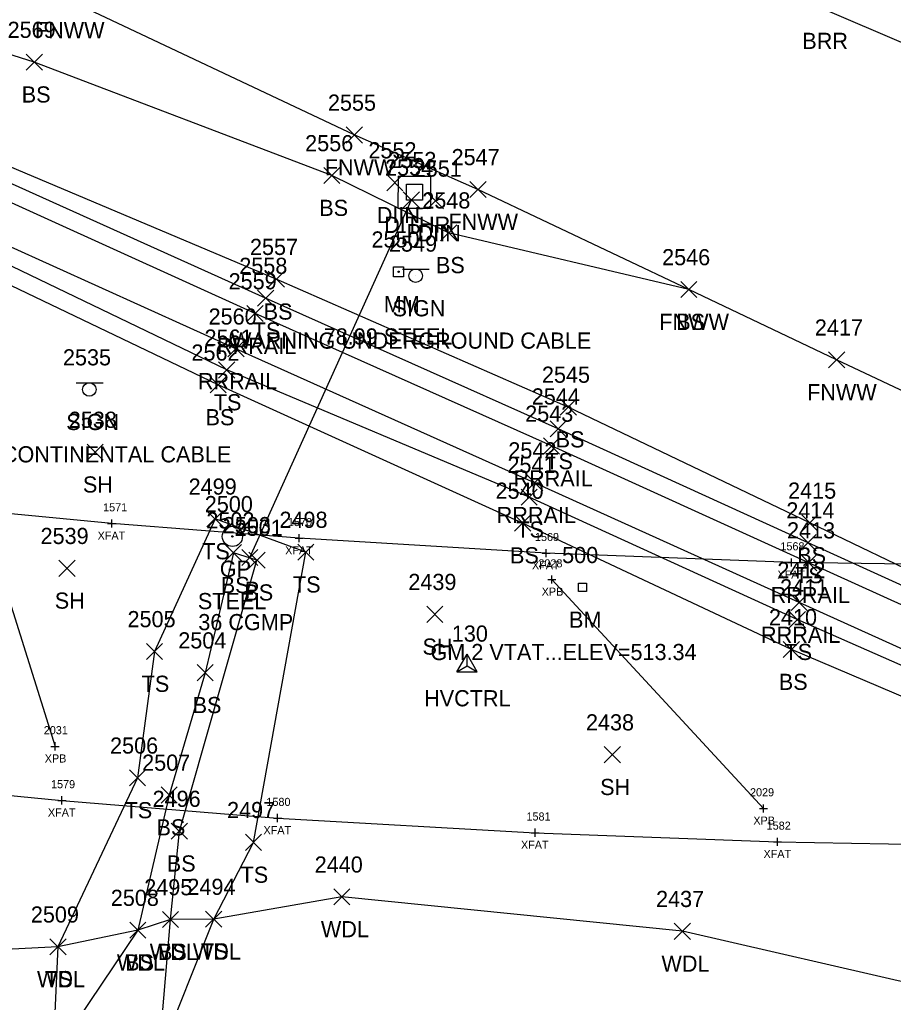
# Model space of a CAD drawing. Extents: x 1599569 to 1610055, y 642560 to 647860.
# Drawn here: x 1601194.8 to 1601302.9, y 647218.7 to 647340.3 of the extents above; entities that cross this region are included whole.
import ezdxf

# ---------------------------------------------------------------- set-up
doc = ezdxf.new("R2010")
doc.units = 0
for name, color, linetype in [('B_A', 7, 'Continuous'), ('B_I', 7, 'Continuous'), ('B_TIC', 7, 'Continuous'), ('BF', 7, 'Continuous'), ('BSUBM', 7, 'Continuous'), ('C_A', 7, 'Continuous'), ('C_C', 7, 'Continuous'), ('C_I', 7, 'Continuous'), ('CPBM', 7, 'Continuous'), ('CPSM', 7, 'Continuous'), ('D_A', 7, 'Continuous'), ('D_C', 7, 'Continuous'), ('D_I', 7, 'Continuous'), ('D_TIC', 7, 'Continuous'), ('DCP', 7, 'Continuous'), ('DS', 7, 'Continuous'), ('L_A', 7, 'Continuous'), ('L_I', 7, 'Continuous'), ('L_TIC', 7, 'Continuous'), ('LABL', 7, 'Continuous'), ('LAWA', 7, 'Continuous'), ('LELB', 7, 'Continuous'), ('LFNC', 7, 'Continuous'), ('R_A', 7, 'Continuous'), ('R_C', 7, 'Continuous'), ('R_I', 7, 'Continuous'), ('R_TIC', 7, 'Continuous'), ('RGP', 7, 'Continuous'), ('RR', 7, 'Continuous'), ('S_A', 7, 'Continuous'), ('S_C', 7, 'Continuous'), ('S_I', 7, 'Continuous'), ('SRM', 7, 'Continuous'), ('SSGN', 7, 'Continuous')]:
    doc.layers.add(name, color=color, linetype=linetype)

msp = doc.modelspace()

# ---------------------------------------------------------------- linework, layer by layer
at = {"layer": 'B_TIC'}
for p, q in [((1601206.23, 647277.99), (1601206.3, 647277.99)), ((1601229.43, 647276.17), (1601229.51, 647276.17)), ((1601259.98, 647274.32), (1601260.05, 647274.32)), ((1601290.34, 647273.17), (1601290.42, 647273.17)), ((1601260.69, 647271.06), (1601260.77, 647271.06)), ((1601199.21, 647250.42), (1601199.29, 647250.42)), ((1601200.08, 647243.74), (1601200.15, 647243.74)), ((1601286.89, 647242.74), (1601286.96, 647242.74)), ((1601226.76, 647241.55), (1601226.84, 647241.55)), ((1601258.62, 647239.74), (1601258.69, 647239.74)), ((1601288.62, 647238.61), (1601288.7, 647238.61))]:
    msp.add_line(p, q, dxfattribs=at)
for points in [[(1601206.22, 647277.49), (1601206.22, 647278.49)], [(1601205.72, 647277.99), (1601206.72, 647277.99)], [(1601228.93, 647276.17), (1601229.93, 647276.17)], [(1601229.43, 647275.67), (1601229.43, 647276.67)], [(1601259.98, 647273.82), (1601259.98, 647274.82)], [(1601259.48, 647274.32), (1601260.48, 647274.32)], [(1601290.34, 647272.67), (1601290.34, 647273.67)], [(1601289.84, 647273.17), (1601290.84, 647273.17)], [(1601260.19, 647271.06), (1601261.19, 647271.06)], [(1601260.69, 647270.56), (1601260.69, 647271.56)], [(1601198.71, 647250.42), (1601199.71, 647250.42)], [(1601199.21, 647249.92), (1601199.21, 647250.92)], [(1601200.07, 647243.24), (1601200.07, 647244.24)], [(1601199.57, 647243.74), (1601200.57, 647243.74)], [(1601286.88, 647242.24), (1601286.88, 647243.24)], [(1601226.76, 647241.05), (1601226.76, 647242.05)], [(1601286.38, 647242.74), (1601287.38, 647242.74)], [(1601226.26, 647241.55), (1601227.26, 647241.55)], [(1601258.11, 647239.74), (1601259.11, 647239.74)], [(1601258.61, 647239.24), (1601258.61, 647240.24)], [(1601288.12, 647238.61), (1601289.12, 647238.61)], [(1601288.62, 647238.11), (1601288.62, 647239.11)]]:
    msp.add_lwpolyline(points, dxfattribs=at)
at = {"layer": 'BF'}
for points in [[(1601321.94, 647272.73), (1601290.34, 647273.17), (1601259.98, 647274.32), (1601229.43, 647276.17), (1601206.22, 647277.99), (1601191.16, 647279.44), (1601163.73, 647282.21), (1601139.85, 647285.25), (1601124.64, 647287.26)], [(1601119.61, 647253.21), (1601149.88, 647249.04), (1601178.06, 647245.86), (1601200.07, 647243.74), (1601226.76, 647241.55), (1601258.61, 647239.74), (1601288.62, 647238.61), (1601320.66, 647238.01)]]:
    msp.add_lwpolyline(points, dxfattribs=at)
at = {"layer": 'BSUBM'}
for points in [[(1601192.25, 647272.5), (1601199.21, 647250.42)], [(1601260.69, 647271.06), (1601286.88, 647242.74)]]:
    msp.add_lwpolyline(points, dxfattribs=at)
at = {"layer": 'CPBM'}
for p, q in [((1601263.99, 647269.59), (1601263.99, 647270.59)), ((1601263.99, 647270.59), (1601264.99, 647270.59)), ((1601264.49, 647270.09), (1601264.49, 647270.09)), ((1601264.49, 647270.09), (1601264.49, 647270.09)), ((1601264.99, 647270.59), (1601264.99, 647269.59)), ((1601264.99, 647269.59), (1601263.99, 647269.59))]:
    msp.add_line(p, q, dxfattribs=at)
at = {"layer": 'CPSM'}
for p, q in [((1601248.94, 647259.65), (1601250.19, 647261.82)), ((1601251.44, 647259.65), (1601250.19, 647261.82)), ((1601250.19, 647260.37), (1601250.19, 647261.82)), ((1601248.94, 647259.65), (1601250.19, 647260.37)), ((1601250.19, 647260.37), (1601250.19, 647260.37)), ((1601250.19, 647260.37), (1601251.44, 647259.65)), ((1601248.94, 647259.65), (1601251.44, 647259.65))]:
    msp.add_line(p, q, dxfattribs=at)
at = {"layer": 'D_TIC'}
for points in [[(1601240.25, 647319.16), (1601242.25, 647321.16)], [(1601242.25, 647319.16), (1601240.25, 647321.16)], [(1601242.31, 647317.03), (1601244.31, 647319.03)], [(1601244.31, 647317.03), (1601242.31, 647319.03)], [(1601245.29, 647316.9), (1601247.29, 647318.9)], [(1601247.29, 647316.9), (1601245.29, 647318.9)], [(1601222.31, 647272.79), (1601224.31, 647274.79)], [(1601224.31, 647272.79), (1601222.31, 647274.79)]]:
    msp.add_lwpolyline(points, dxfattribs=at)
at = {"layer": 'DCP'}
msp.add_lwpolyline([(1601223.31, 647273.79), (1601243.31, 647318.03)], dxfattribs=at)
at = {"layer": 'DS'}
for p, q in [((1601241.69, 647320.98), (1601245.69, 647320.98)), ((1601241.69, 647316.98), (1601241.71, 647320.98)), ((1601245.69, 647320.98), (1601245.69, 647316.98)), ((1601242.69, 647319.98), (1601244.69, 647319.98)), ((1601242.69, 647317.98), (1601242.69, 647319.98)), ((1601244.69, 647319.98), (1601244.69, 647317.98)), ((1601243.7, 647318.99), (1601243.7, 647318.99)), ((1601244.69, 647317.98), (1601242.69, 647317.98)), ((1601245.69, 647316.98), (1601241.69, 647316.98)), ((1601244.19, 647316.98), (1601244.69, 647316.98))]:
    msp.add_line(p, q, dxfattribs=at)
at = {"layer": 'L_TIC'}
for points in [[(1601195.65, 647334.07), (1601197.65, 647336.07)], [(1601197.65, 647334.07), (1601195.65, 647336.07)], [(1601235.24, 647325.06), (1601237.24, 647327.06)], [(1601237.24, 647325.06), (1601235.24, 647327.06)], [(1601232.47, 647320.04), (1601234.47, 647322.04)], [(1601234.47, 647320.04), (1601232.47, 647322.04)], [(1601250.54, 647318.32), (1601252.54, 647320.32)], [(1601252.54, 647318.32), (1601250.54, 647320.32)], [(1601246.91, 647312.96), (1601248.91, 647314.96)], [(1601248.91, 647312.96), (1601246.91, 647314.96)], [(1601225.59, 647307.21), (1601227.59, 647309.21)], [(1601227.59, 647307.21), (1601225.59, 647309.21)], [(1601276.64, 647305.94), (1601278.64, 647307.94)], [(1601278.64, 647305.94), (1601276.64, 647307.94)], [(1601276.64, 647305.94), (1601278.64, 647307.94)], [(1601278.64, 647305.94), (1601276.64, 647307.94)], [(1601224.27, 647304.87), (1601226.27, 647306.87)], [(1601226.27, 647304.87), (1601224.27, 647306.87)], [(1601294.93, 647297.24), (1601296.93, 647299.24)], [(1601296.93, 647297.24), (1601294.93, 647299.24)], [(1601219.45, 647295.99), (1601221.45, 647297.99)], [(1601221.45, 647295.99), (1601219.45, 647297.99)], [(1601218.4, 647294.14), (1601220.4, 647296.14)], [(1601220.4, 647294.14), (1601218.4, 647296.14)], [(1601261.72, 647291.4), (1601263.72, 647293.4)], [(1601263.72, 647291.4), (1601261.72, 647293.4)], [(1601260.46, 647288.71), (1601262.46, 647290.71)], [(1601262.46, 647288.71), (1601260.46, 647290.71)], [(1601203.17, 647285.82), (1601205.17, 647287.82)], [(1601205.17, 647285.82), (1601203.17, 647287.82)], [(1601256.88, 647280.25), (1601258.88, 647282.25)], [(1601258.88, 647280.25), (1601256.88, 647282.25)], [(1601218.01, 647277.56), (1601220.01, 647279.56)], [(1601220.01, 647277.56), (1601218.01, 647279.56)], [(1601256.07, 647277.05), (1601258.07, 647279.05)], [(1601258.07, 647277.05), (1601256.07, 647279.05)], [(1601291.61, 647277.06), (1601293.61, 647279.06)], [(1601293.61, 647277.06), (1601291.61, 647279.06)], [(1601291.39, 647274.61), (1601293.39, 647276.61)], [(1601293.39, 647274.61), (1601291.39, 647276.61)], [(1601220.28, 647273.38), (1601222.28, 647275.38)], [(1601222.28, 647273.38), (1601220.28, 647275.38)], [(1601229.24, 647273.45), (1601231.24, 647275.45)], [(1601231.24, 647273.45), (1601229.24, 647275.45)], [(1601199.69, 647271.45), (1601201.69, 647273.45)], [(1601201.69, 647271.45), (1601199.69, 647273.45)], [(1601223.2, 647272.46), (1601225.2, 647274.46)], [(1601225.2, 647272.46), (1601223.2, 647274.46)], [(1601245.2, 647265.76), (1601247.2, 647267.76)], [(1601247.2, 647265.76), (1601245.2, 647267.76)], [(1601290.06, 647265.1), (1601292.06, 647267.1)], [(1601292.06, 647265.1), (1601290.06, 647267.1)], [(1601210.52, 647261.16), (1601212.52, 647263.16)], [(1601212.52, 647261.16), (1601210.52, 647263.16)], [(1601289.33, 647261.4), (1601291.33, 647263.4)], [(1601291.33, 647261.4), (1601289.33, 647263.4)], [(1601216.79, 647258.53), (1601218.79, 647260.53)], [(1601218.79, 647258.53), (1601216.79, 647260.53)], [(1601267.17, 647248.39), (1601269.17, 647250.39)], [(1601269.17, 647248.39), (1601267.17, 647250.39)], [(1601208.41, 647245.52), (1601210.41, 647247.52)], [(1601210.41, 647245.52), (1601208.41, 647247.52)], [(1601212.33, 647243.4), (1601214.33, 647245.4)], [(1601214.33, 647243.4), (1601212.33, 647245.4)], [(1601213.6, 647238.93), (1601215.6, 647240.93)], [(1601215.6, 647238.93), (1601213.6, 647240.93)], [(1601222.76, 647237.54), (1601224.76, 647239.54)], [(1601224.76, 647237.54), (1601222.76, 647239.54)], [(1601233.69, 647230.8), (1601235.69, 647232.8)], [(1601235.69, 647230.8), (1601233.69, 647232.8)], [(1601212.51, 647227.99), (1601214.51, 647229.99)], [(1601214.51, 647227.99), (1601212.51, 647229.99)], [(1601212.51, 647227.99), (1601214.51, 647229.99)], [(1601214.51, 647227.99), (1601212.51, 647229.99)], [(1601217.85, 647228.04), (1601219.85, 647230.04)], [(1601219.85, 647228.04), (1601217.85, 647230.04)], [(1601217.85, 647228.04), (1601219.85, 647230.04)], [(1601219.85, 647228.04), (1601217.85, 647230.04)], [(1601208.45, 647226.68), (1601210.45, 647228.68)], [(1601210.45, 647226.68), (1601208.45, 647228.68)], [(1601208.45, 647226.68), (1601210.45, 647228.68)], [(1601210.45, 647226.68), (1601208.45, 647228.68)], [(1601275.84, 647226.54), (1601277.84, 647228.54)], [(1601277.84, 647226.54), (1601275.84, 647228.54)], [(1601198.57, 647224.62), (1601200.57, 647226.62)], [(1601200.57, 647224.62), (1601198.57, 647226.62)], [(1601198.57, 647224.62), (1601200.57, 647226.62)], [(1601200.57, 647224.62), (1601198.57, 647226.62)]]:
    msp.add_lwpolyline(points, dxfattribs=at)
at = {"layer": 'LABL'}
msp.add_lwpolyline([(1601168.99, 647399.27), (1601207.41, 647380.73), (1601257.17, 647358.28), (1601294.19, 647341.7), (1601346.91, 647319.14), (1601374.73, 647304.92), (1601415.9, 647287.21), (1601447.46, 647269.36), (1601451.82, 647260.74), (1601445.32, 647247.33), (1601438.38, 647230.38)], dxfattribs=at)
at = {"layer": 'LAWA'}
msp.add_lwpolyline([(1601306.6, 647220.69), (1601276.84, 647227.54), (1601234.69, 647231.8), (1601218.85, 647229.04), (1601213.51, 647228.99), (1601209.45, 647227.68), (1601199.57, 647225.62), (1601172.91, 647224.25), (1601154.16, 647223.84), (1601131.9, 647227.51), (1601118.99, 647241.56), (1601106.98, 647246.07), (1601045.88, 647251.39), (1601009.79, 647259.81), (1600973.15, 647266.08), (1600946.11, 647265.67), (1600904.1, 647280.51), (1600862.74, 647296.26), (1600826.18, 647313.68), (1600771.19, 647334.59)], dxfattribs=at)
at = {"layer": 'LELB'}
for points in [[(1601329.86, 647260.18), (1601292.61, 647278.06), (1601262.72, 647292.4), (1601226.59, 647308.21), (1601190.68, 647323.36), (1601158.75, 647338.43), (1601129.91, 647351.62), (1601096.68, 647366.43), (1601056.58, 647384.54), (1601012.74, 647404.18), (1600965.22, 647426.07), (1600914.49, 647448.77), (1600866.79, 647471.13), (1600821.34, 647492.23), (1600763.72, 647518.52)], [(1601329.08, 647258.95), (1601292.39, 647275.61), (1601261.46, 647289.71), (1601225.27, 647305.87), (1601190.14, 647321.67), (1601157.62, 647336.35), (1601128.98, 647349.36), (1601095.53, 647364.39), (1601055.96, 647382.57), (1601011.7, 647402.22), (1600964.35, 647423.93), (1600913.28, 647446.74), (1600865.78, 647468.67), (1600819.14, 647488.99), (1600762.95, 647515.26)], [(1601326.17, 647250.65), (1601291.06, 647266.1), (1601257.88, 647281.25), (1601220.45, 647296.99), (1601187.26, 647312.94), (1601153.32, 647328.3), (1601124.87, 647340.95), (1601091.41, 647355.79), (1601053.43, 647373.03), (1601007.18, 647393.84), (1600960.43, 647415.03), (1600909.23, 647438.57), (1600861.95, 647459.92), (1600814.78, 647480.92), (1600758.97, 647506.06)], [(1601324.87, 647247.72), (1601290.33, 647262.4), (1601257.07, 647278.05), (1601219.4, 647295.14), (1601185.88, 647311.18), (1601152.37, 647326.07), (1601123.71, 647338.45), (1601090.36, 647353.63), (1601052.5, 647371.13), (1601006, 647391.96), (1600959.19, 647412.11), (1600907.65, 647435.58), (1600860.78, 647455.97), (1600813.3, 647477.78), (1600757.71, 647501.96)], [(1601277.64, 647306.94), (1601247.91, 647313.96), (1601233.47, 647321.04), (1601196.65, 647335.07), (1601162.36, 647345.97), (1601131.17, 647354.49), (1601097.9, 647368.75), (1601057.17, 647386.63), (1601013.7, 647406.22), (1600966.1, 647427.78), (1600916.08, 647451.44), (1600867.43, 647472.68), (1600824.54, 647496.94)], [(1601212.04, 647211.96), (1601218.85, 647229.04), (1601223.76, 647238.54), (1601230.24, 647274.45), (1601219.01, 647278.56), (1601211.52, 647262.16), (1601209.41, 647246.52), (1601199.57, 647225.62), (1601198.93, 647212.03)], [(1601311.97, 647149.61), (1601287.9, 647169.52), (1601262.65, 647185.13), (1601246.21, 647197.47), (1601212.04, 647211.96), (1601213.51, 647228.99), (1601214.6, 647239.93), (1601224.2, 647273.46), (1601221.28, 647274.38), (1601217.79, 647259.53), (1601213.33, 647244.4), (1601209.45, 647227.68), (1601198.93, 647212.03), (1601175.4, 647204.46), (1601147.05, 647198.15), (1601097.33, 647185.37), (1601055.4, 647199.51), (1601019.79, 647208.33), (1600981.66, 647213.12), (1600949.35, 647228.64)]]:
    msp.add_lwpolyline(points, dxfattribs=at)
at = {"layer": 'LFNC'}
msp.add_lwpolyline([(1601438.38, 647230.38), (1601406.08, 647246.23), (1601390.36, 647253.65), (1601325.07, 647284.52), (1601295.93, 647298.24), (1601277.64, 647306.94), (1601251.54, 647319.32), (1601236.24, 647326.06), (1601200.38, 647343.03), (1601163.89, 647358.89), (1601138.18, 647369.81), (1601105.25, 647383.87), (1601061.33, 647402.55), (1601021.95, 647420.15), (1600970.86, 647443.1), (1600923.39, 647465.04), (1600876.08, 647486.37)], dxfattribs=at)
at = {"layer": 'R_TIC'}
for points in [[(1601222.96, 647302.96), (1601224.96, 647304.96)], [(1601224.96, 647302.96), (1601222.96, 647304.96)], [(1601220.6, 647298.6), (1601222.6, 647300.6)], [(1601222.6, 647298.6), (1601220.6, 647300.6)], [(1601259.65, 647286.58), (1601261.65, 647288.58)], [(1601261.65, 647286.58), (1601259.65, 647288.58)], [(1601257.56, 647282.04), (1601259.56, 647284.04)], [(1601259.56, 647282.04), (1601257.56, 647284.04)], [(1601291.48, 647272.14), (1601293.48, 647274.14)], [(1601293.48, 647272.14), (1601291.48, 647274.14)], [(1601290.28, 647267.22), (1601292.28, 647269.22)], [(1601292.28, 647267.22), (1601290.28, 647269.22)]]:
    msp.add_lwpolyline(points, dxfattribs=at)
at = {"layer": 'RGP'}
msp.add_line((1601221.16, 647276.39), (1601221.16, 647276.39), dxfattribs=at)
for radius in [1.25, 0.0833]:
    msp.add_circle((1601221.16, 647276.39), radius, dxfattribs=at)
at = {"layer": 'RR'}
for points in [[(1601328.26, 647256.93), (1601292.48, 647273.14), (1601260.65, 647287.58), (1601223.96, 647303.96), (1601189.34, 647319.67), (1601156.57, 647334.47), (1601128.05, 647347.29), (1601094.57, 647362.49), (1601054.86, 647380.37), (1601010.55, 647400.2), (1600963.24, 647421.51), (1600912.09, 647444.53), (1600864.46, 647466.02), (1600817.98, 647486.96), (1600761.67, 647512.45)], [(1601326.5, 647252.29), (1601291.28, 647268.22), (1601258.56, 647283.04), (1601221.6, 647299.6), (1601187.65, 647314.96), (1601154.54, 647329.95), (1601125.78, 647342.91), (1601092.45, 647357.88), (1601054.06, 647375.24), (1601008.5, 647395.78), (1600961.24, 647417), (1600909.88, 647440.14), (1600862.44, 647461.47), (1600815.63, 647482.59), (1600759.94, 647507.87)]]:
    msp.add_lwpolyline(points, dxfattribs=at)
at = {"layer": 'SRM'}
msp.add_lwpolyline([(1601241.09, 647309.75), (1601242.34, 647309.75), (1601242.34, 647308.5), (1601241.09, 647308.5)], close=True, dxfattribs=at)
msp.add_circle((1601241.72, 647309.13), 0.0833, dxfattribs=at)
at = {"layer": 'SSGN'}
for p, q in [((1601242.19, 647309.47), (1601245.52, 647309.47)), ((1601243.83, 647308.64), (1601243.83, 647308.64)), ((1601201.82, 647295.4), (1601205.15, 647295.4)), ((1601203.46, 647294.57), (1601203.46, 647294.57))]:
    msp.add_line(p, q, dxfattribs=at)
for centre in [(1601243.83, 647308.64), (1601203.46, 647294.57)]:
    msp.add_circle(centre, 0.833, dxfattribs=at)

# ---------------------------------------------------------------- texts
at = {"layer": 'B_A'}
for s, p in [('XFAT', (1601204.48, 647275.99)), ('XFAT', (1601227.69, 647274.17)), ('XFAT', (1601258.23, 647272.32)), ('XFAT', (1601288.6, 647271.17)), ('XPB', (1601259.43, 647269.06)), ('XPB', (1601197.94, 647248.42)), ('XFAT', (1601198.33, 647241.74)), ('XPB', (1601285.62, 647240.74)), ('XFAT', (1601225.01, 647239.55)), ('XFAT', (1601256.87, 647237.74)), ('XFAT', (1601286.88, 647236.61))]:
    msp.add_text(s, height=1, dxfattribs=at).set_placement(p)
at = {"layer": 'B_I'}
for s, p in [('1571', (1601205.16, 647279.49)), ('1570', (1601228.04, 647277.67)), ('1569', (1601258.6, 647275.82)), ('1568', (1601288.97, 647274.67)), ('2028', (1601259.02, 647272.56)), ('2031', (1601197.82, 647251.92)), ('1579', (1601198.72, 647245.24)), ('2029', (1601285.21, 647244.24)), ('1580', (1601225.37, 647243.05)), ('1581', (1601257.55, 647241.24)), ('1582', (1601287.27, 647240.11))]:
    msp.add_text(s, height=1, dxfattribs=at).set_placement(p)
at = {"layer": 'C_A'}
for s, p in [('BM', (1601262.81, 647265.09)), ('HVCTRL', (1601244.88, 647255.37))]:
    msp.add_text(s, height=2, dxfattribs=at).set_placement(p)
at = {"layer": 'C_C'}
msp.add_text('GM 2 VTAT...ELEV=513.34', height=2, dxfattribs=at).set_placement((1601245.67, 647261.09))
at = {"layer": 'C_I'}
for s, p in [('500', (1601261.96, 647273.09)), ('130', (1601248.31, 647263.37))]:
    msp.add_text(s, height=2, dxfattribs=at).set_placement(p)
at = {"layer": 'D_A'}
for s, p in [('DIIN', (1601239.02, 647315.16)), ('DITHR', (1601239.94, 647313.96)), ('P', (1601242.69, 647313.03)), ('DIIN', (1601244.07, 647312.9)), ('P', (1601222.69, 647268.79))]:
    msp.add_text(s, height=2, dxfattribs=at).set_placement(p)
at = {"layer": 'D_C'}
msp.add_text('36 CGMP', height=2, dxfattribs=at).set_placement((1601216.94, 647264.79))
at = {"layer": 'D_I'}
for s, p in [('2552', (1601237.99, 647323.16)), ('2553', (1601240.45, 647321.96)), ('2554', (1601240.05, 647321.03)), ('2551', (1601243.6, 647320.9)), ('2503', (1601219.97, 647276.79))]:
    msp.add_text(s, height=2, dxfattribs=at).set_placement(p)
at = {"layer": 'L_A'}
for s, p in [('FNWW', (1601196.72, 647338.03)), ('BRR', (1601291.68, 647336.7)), ('BS', (1601195.09, 647330.07)), ('FNWW', (1601232.59, 647321.06)), ('BS', (1601231.91, 647316.04)), ('FNWW', (1601247.89, 647314.32)), ('BS', (1601246.35, 647308.96)), ('BS', (1601225.03, 647303.21)), ('FNWW', (1601273.99, 647301.94)), ('BS', (1601276.08, 647301.94)), ('TS', (1601223.68, 647300.87)), ('FNWW', (1601292.27, 647293.24)), ('TS', (1601218.86, 647291.99)), ('BS', (1601217.84, 647290.14)), ('BS', (1601261.16, 647287.4)), ('TS', (1601259.87, 647284.71)), ('SH', (1601202.66, 647281.82)), ('TS', (1601256.29, 647276.25)), ('TS', (1601217.42, 647273.56)), ('BS', (1601255.51, 647273.05)), ('BS', (1601291.05, 647273.06)), ('TS', (1601290.8, 647270.61)), ('BS', (1601219.72, 647269.38)), ('TS', (1601228.65, 647269.45)), ('BS', (1601222.64, 647268.46)), ('SH', (1601199.18, 647267.45)), ('SH', (1601244.68, 647261.76)), ('TS', (1601289.47, 647261.1)), ('TS', (1601209.93, 647257.16)), ('BS', (1601288.77, 647257.4)), ('BS', (1601216.24, 647254.53)), ('SH', (1601266.66, 647244.39)), ('TS', (1601207.82, 647241.52)), ('BS', (1601211.77, 647239.4)), ('BS', (1601213.04, 647234.93)), ('TS', (1601222.17, 647233.54)), ('WDL', (1601232.11, 647226.8)), ('WDL', (1601210.93, 647223.99)), ('BS', (1601211.95, 647223.99)), ('WDL', (1601216.27, 647224.04)), ('TS', (1601217.26, 647224.04)), ('WDL', (1601206.87, 647222.68)), ('BS', (1601207.89, 647222.68)), ('WDL', (1601274.25, 647222.54)), ('WDL', (1601196.98, 647220.62)), ('TS', (1601197.97, 647220.62))]:
    msp.add_text(s, height=2, dxfattribs=at).set_placement(p)
at = {"layer": 'L_I'}
for s, p in [('2569', (1601193.34, 647338.07)), ('2555', (1601232.98, 647329.06)), ('2556', (1601230.16, 647324.04)), ('2547', (1601248.28, 647322.32)), ('2548', (1601244.65, 647316.96)), ('2557', (1601223.33, 647311.21)), ('2546', (1601274.33, 647309.94)), ('2546', (1601274.33, 647309.94)), ('2558', (1601222.01, 647308.87)), ('2417', (1601293.23, 647301.24)), ('2561', (1601217.71, 647299.99)), ('2562', (1601216.09, 647298.14)), ('2545', (1601259.46, 647295.4)), ('2544', (1601258.2, 647292.71)), ('2538', (1601200.91, 647289.82)), ('2541', (1601255.19, 647284.25)), ('2499', (1601215.74, 647281.56)), ('2540', (1601253.72, 647281.05)), ('2415', (1601289.92, 647281.06)), ('2414', (1601289.7, 647278.61)), ('2502', (1601217.94, 647277.38)), ('2498', (1601226.98, 647277.45)), ('2501', (1601221.43, 647276.46)), ('2539', (1601197.42, 647275.45)), ('2439', (1601242.93, 647269.76)), ('2411', (1601288.93, 647269.1)), ('2410', (1601287.55, 647265.4)), ('2505', (1601208.18, 647265.16)), ('2504', (1601214.46, 647262.53)), ('2438', (1601264.91, 647252.39)), ('2506', (1601206.02, 647249.52)), ('2507', (1601209.99, 647247.4)), ('2496', (1601211.28, 647242.93)), ('2497', (1601220.5, 647241.54)), ('2440', (1601231.34, 647234.8)), ('2495', (1601210.25, 647231.99)), ('2495', (1601210.25, 647231.99)), ('2494', (1601215.59, 647232.04)), ('2494', (1601215.59, 647232.04)), ('2508', (1601206.11, 647230.68)), ('2508', (1601206.11, 647230.68)), ('2437', (1601273.58, 647230.54)), ('2509', (1601196.22, 647228.62)), ('2509', (1601196.22, 647228.62))]:
    msp.add_text(s, height=2, dxfattribs=at).set_placement(p)
at = {"layer": 'R_A'}
for s, p in [('RRRAIL', (1601219.25, 647298.96)), ('RRRAIL', (1601216.89, 647294.6)), ('RRRAIL', (1601255.94, 647282.58)), ('RRRAIL', (1601253.86, 647278.04)), ('GP', (1601219.6, 647271.39)), ('RRRAIL', (1601287.77, 647268.14)), ('RRRAIL', (1601286.57, 647263.22))]:
    msp.add_text(s, height=2, dxfattribs=at).set_placement(p)
at = {"layer": 'R_C'}
msp.add_text('STEEL', height=2, dxfattribs=at).set_placement((1601216.88, 647267.39))
at = {"layer": 'R_I'}
for s, p in [('2559', (1601220.69, 647306.96)), ('2560', (1601218.21, 647302.6)), ('2543', (1601257.39, 647290.58)), ('2542', (1601255.3, 647286.04)), ('2500', (1601217.74, 647279.39)), ('2413', (1601289.79, 647276.14)), ('2412', (1601288.59, 647271.22))]:
    msp.add_text(s, height=2, dxfattribs=at).set_placement(p)
at = {"layer": 'S_A'}
for s, p in [('MM', (1601239.9, 647304.13)), ('SIGN', (1601240.97, 647303.62)), ('SIGN', (1601200.6, 647289.55))]:
    msp.add_text(s, height=2, dxfattribs=at).set_placement(p)
at = {"layer": 'S_C'}
for s, p in [('WARNING UNDERGROUND CABLE', (1601220.98, 647299.62)), ('78.99 STEEL', (1601232.46, 647300.13)), ('TRANSCONTINENTAL CABLE', (1601183.57, 647285.55))]:
    msp.add_text(s, height=2, dxfattribs=at).set_placement(p)
at = {"layer": 'S_I'}
for s, p in [('2550', (1601238.37, 647312.13)), ('2549', (1601240.54, 647311.62)), ('2535', (1601200.19, 647297.55))]:
    msp.add_text(s, height=2, dxfattribs=at).set_placement(p)

doc.saveas('drawing.dxf')
